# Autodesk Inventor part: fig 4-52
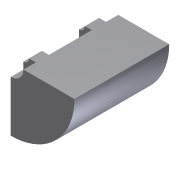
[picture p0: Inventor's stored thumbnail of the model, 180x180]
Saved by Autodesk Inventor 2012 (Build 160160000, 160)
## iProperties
Created: 2010-02
Part Number: fig 4-52
Document SubType Name: Modeling
Designer: CADSoft
Density: 1 g/cm^3
Material: Default
Author: CADSoft
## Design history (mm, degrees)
sketch "Sketch1"
  geometry: L1 (4.005, 30.039)-(20.155, 30.039); L2 (20.155, 30.039)-(20.155, 0); L3 (20.155, 0)-(4.005, 0); L4 (4.005, 26.163)-(1.809, 26.163); L5 (1.809, 26.163)-(1.809, 21.641); L6 (1.809, 21.641)-(4.005, 21.641); L7 (4.005, 3.941)-(1.809, 3.941); L8 (1.809, 3.941)-(1.809, 8.075); L9 (1.809, 8.075)-(4.005, 8.075); L10 (4.005, 26.163)-(4.005, 30.039); L11 (4.005, 0)-(4.005, 3.941); L12 (4.005, 8.075)-(4.005, 21.641); L13 (0, 31.977)-(0, -5.62); 1 further point
  constraints: 26 end point
revolve "Revolution1" sketch "Sketch1" stored, may be unused: angle "d0" = 90 deg
body "Solid1"
